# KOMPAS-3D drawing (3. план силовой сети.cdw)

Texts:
  ДП.11.213.04.000.00.ЭМ
  Телятник на 120 голов в СПК колхоз "Дзержинского" Даниловского МР Ярославской обл.
  УСЛОВНЫЕ ОБОЗНАЧЕНИЯ:
  - пульт распределительнай марки ПР8503-002
  - линия силовой электропроводки.
  № поз.
  Наименование помещения
  Площадь,
  Стойловое
  Веткабинет
  Инвентарная
  Венткамера
  Электрощитовая
  Служебная
  Санузел
  Кладовая дезосредств
  Фуражная
  Помещение для приготовления ЗЦМ
  Помещение для погрузки навоза в ТС
  Коридор
  ЭКСПЛИКАЦИЯ ПОМЕЩЕНИЙ:
  ЯОУ-8501
  ввод в здание
  - ящик осветительный марки ЯОУ - 8501, рассчитанный
  на 6 отходящих групп освещения.
  - нагревательный элемент  номер по плану  мощность, кВт
  - электродвигатель  номер по плану  мощность, кВт
  ПР85-067
  - пульт управления комплектной установкой
  ВВГ (4 х 1,5)
  ВВГ (4 х 6,0)
  ВВГ (5 х 1,5)
  ВВГ (4 х 10)
  заливка
  Куракин
  ФГОУ ВПО ЯГСХА
  Телятник на 120 голов
  в СПК колхоз "Дзержинского"
  Даниловского МР Ярославской обл.
  Шмигель
  План силовой сети.
  ДП08Ф040200009Э0-
  Королёва
  Орлов
Dimensions and other numbers on the sheet: 1; 2; 3; 4; 5; 6; 7; 8; 9; 10; 11; 12; 504; 16,6; 15,7; 29,5; 11,0; 25,0; 3,8; 12,2; 14,7; 27,5; 22,4; 30,1; 12000; 42000; 30000; 6000; 4500; 2 группа, ТСН - 160; 1 группа, ЭВП-1; 3 группа, АЗМ-0,8; 4 группа, УАП-400/0,9; 5 группа, СФОЦ-25/0,5-И1; 6 группа, освещение; 1:100; 0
